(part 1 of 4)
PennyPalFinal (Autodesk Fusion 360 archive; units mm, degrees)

design "PennyPalFinal" references "switch", "boost", "PCB&CoinChute1", "battery snap fit", "annular-snap-speaker1", "solenoid", "mainPCB"
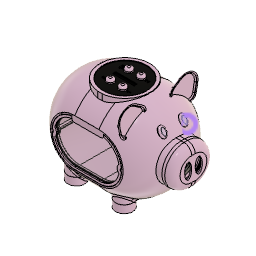
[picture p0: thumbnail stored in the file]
part number: 2026-05-30-10-11-40-978
part number: 2026-05-16-19-25-30-712
description: KiCad electronic assembly
part number: 2026-05-24-18-37-49-600
description: Part Number
part number: 2026-05-24-11-27-49-518
part number: 2026-05-24-18-37-49-601
sketch "piggysketch" plane through (0, 0, 0) normal (0, 0, 1) x axis (1, 0, 0)
  line L1 (-82.5, -65) -> (82.5, -65)
  line L2 (-82.5, 65) -> (-82.5, -65)
  line L3 (82.5, 65) -> (-82.5, 65)
  line L4 (82.5, -65) -> (82.5, 65)
  line L5 (-82.5, 65) -> (82.5, -65)
  line L6 (82.5, 65) -> (-82.5, -65)
  line L7 (82.5, 0) -> (-82.5, 0)
  circle C1 centre (-17.5, 0) radius 65
  circle C2 centre (17.5, 0) radius 65
  point P6 (0, 0)
  point P1 (0, 0)
  point P9 (-82.5, 0)
  point P10 (82.5, 0)
  point P4 (-82.5, 65)
  point P5 (82.5, 65)
  point P3 (-82.5, -65)
  horizontal L1
  perpendicular L1 L2
  parallel L1 L3
  parallel L2 L4
  coincident L5 P6
  coincident L6 P6
  coincident P1 P6
  midpoint L2 P9
  midpoint L4 P10
  dimension "d1" distance P4 P5 = 165
  dimension "d2" distance P3 P4 = 130
  dimension "d3" diameter C1 = 130
  dimension "d4" diameter C2 = 130
revolve "Revolve1" sketch "piggysketch" AlongAngle 360
shell "Shell1" innerThickness 2
work_plane "WorkPlane1" AlongDistance 83
sketch "facesketch" plane through (83, 0, 0) normal (1, 0, 0) x axis (0, 1, 0)
  line L1 (-30, -22.5) -> (30, -22.5)
  line L2 (-30, 22.5) -> (-30, -22.5)
  line L3 (30, 22.5) -> (-30, 22.5)
  line L4 (30, -22.5) -> (30, 22.5)
  line L5 (30, 22.5) -> (-30, -22.5)
  line L6 (30, 0) -> (-30, 0)
  line L7 (-30, 0) -> (0, 0)
  line L8 (-29.1264, 64.0008) -> (-30, 0)
  line L9 (0, 65.16) -> (-29.1264, 64.0008)
  line L10 (0, 0) -> (0, 65.16)
  line L11 (0, 32.58) -> (-30, 32.58)
  line L12 (-15, 22.5) -> (-15, 65.16)
  line L13 (-15, 0) -> (-15, 21.2132)
  line L14 (-29.4017, 43.83) -> (-15, 43.83)
  curve K1 (-15, 42.5) -> (-15, 27.5)
  curve K2 (-20.3395, 35) -> (-9.6605, 35)
  line L15 (-44.7548, 40.1162) -> (-26.9747, 52.3166)
  line L16 (-62.3715, 58.4644) -> (-60.0051, 46.3533)
  line L17 (-27.0389, 69.0425) -> (-36.629, 75.5154)
  line L18 (-49.3045, 79.4031) -> (-31.4219, 51.5006)
  line L19 (-60.4086, 58.848) -> (-58.0422, 46.7368)
  line L20 (-28.1577, 67.3848) -> (-37.748, 73.8577)
  line L21 (-45.8864, 41.7654) -> (-28.1062, 53.9657)
  line L22 (27.3032, -17.9046) -> (27.9578, -18.4233)
  line L23 (31.5266, -21.1565) -> (30.8609, -20.6522)
  line L24 (28.7497, -21.5623) -> (30, -22.5)
  line L25 (-30, 22.5) -> (26.794, -20.0955)
  line L26 (-27.3032, -17.9046) -> (-27.9578, -18.4233)
  line L27 (-31.5266, -21.1565) -> (-30.8609, -20.6522)
  circle C1 centre (-7.5, 0) radius 22.5
  circle C2 centre (7.5, 0) radius 22.5
  closed curve K3 centre (-15, 35)
  closed curve K4 centre (15, 35)
  arc A1 centre (-50.3315, 48.2434) radius 9.8565 clockwise from (-44.7548, 40.1162) to (-60.0051, 46.3533)
  arc A2 centre (-32.6982, 60.6577) radius 10.116 clockwise from (-27.0389, 69.0425) to (-26.9747, 52.3166)
  arc A3 centre (-45.9752, 61.6681) radius 16.7063 clockwise from (-62.3715, 58.4644) to (-36.629, 75.5154)
  arc A4 centre (-45.9752, 61.6681) radius 14.7063 clockwise from (-60.4086, 58.848) to (-37.748, 73.8577)
  arc A5 centre (-32.6982, 60.6577) radius 8.116 clockwise from (-28.1577, 67.3848) to (-28.1062, 53.9657)
  arc A6 centre (-50.3315, 48.2434) radius 7.8565 clockwise from (-45.8864, 41.7654) to (-58.0422, 46.7368)
  arc A7 centre (29.4022, -19.5471) radius 1.8301 clockwise from (30.8609, -20.6522) to (27.9578, -18.4233)
  arc A8 centre (29.4022, -19.5471) radius 2.6652 clockwise from (27.206, -21.0572) to (27.3032, -17.9046)
  arc A9 centre (29.4022, -19.5471) radius 2.6652 clockwise from (31.5266, -21.1565) to (28.3703, -22.0045)
  arc A10 centre (-29.4022, -19.5471) radius 1.8301 clockwise from (-27.9578, -18.4233) to (-30.8609, -20.6522)
  arc A11 centre (-29.4022, -19.5471) radius 2.6652 clockwise from (-27.3032, -17.9046) to (-27.206, -21.0572)
  arc A12 centre (-29.4022, -19.5471) radius 2.6652 clockwise from (-28.3703, -22.0045) to (-31.5266, -21.1565)
  arc A13 centre (0, 2.7271) radius 37.6367 clockwise from (28.3703, -22.0045) to (-28.3703, -22.0045)
  arc A14 centre (0, 2.7271) radius 36.1367 clockwise from (27.206, -21.0572) to (-27.206, -21.0572)
  point P6 (0, 0)
  point P1 (0, 0)
  point P7 (-30, 0)
  point P8 (30, 0)
  point P11 (0, 0)
  point P16 (0, 32.58)
  point P18 (-15, 0)
  point P19 (-15, 22.5)
  point P20 (-15, 21.2132)
  point P21 (-15, 43.83)
  point P22 (-29.4017, 43.83)
  point P24 (-15, 27.5)
  point P25 (-15, 42.5)
  point P26 (-9.6605, 35)
  point P27 (-20.3395, 35)
  point P23 (-15, 35)
  point P57 (26.794, -20.0955)
  point P51 (27.3032, -17.9046)
  point P64 (-27.3032, -17.9046)
  point P52 (31.5266, -21.1565)
  point P66 (-31.5266, -21.1565)
  point P53 (27.9578, -18.4233)
  point P61 (-27.9578, -18.4233)
  point P54 (30.8609, -20.6522)
  point P62 (-30.8609, -20.6522)
  point P55 (27.206, -21.0572)
  point P65 (-27.206, -21.0572)
  point P58 (28.3703, -22.0045)
  point P68 (-28.3703, -22.0045)
  point P4 (-30, 22.5)
  point P5 (30, 22.5)
  point P3 (-30, -22.5)
  horizontal L1
  perpendicular L1 L2
  parallel L1 L3
  parallel L2 L4
  coincident P6 L25
  coincident L5 P6
  coincident P1 P6
  midpoint L2 P7
  midpoint L4 P8
  coincident P7 C1
  coincident P8 C2
  horizontal L7
  vertical L10
  coincident P6 P11
  midpoint L10 P16
  midpoint L7 P18
  tangent C2 L13
  coincident L3 P19
  coincident C1 P20
  collinear L12 L13
  midpoint L12 P21
  coincident L8 P22
  coincident K3 P24
  coincident K3 P25
  coincident K3 P26
  coincident K3 P27
  coincident L12 P23
  perpendicular L14 K1
  symmetric L10 K3 K4
  tangent L15 A1
  tangent L16 A1
  tangent L15 A2
  tangent L17 A2
  tangent L16 A3
  tangent L17 A3
  concentric A7 A8
  collinear L24 L25
  coincident P57 A8
  concentric A8 A9
  symmetric L10 P51 P64
  symmetric L10 P52 P66
  symmetric L10 P53 P61
  symmetric L10 A7 A10
  symmetric L10 P54 P62
  symmetric L10 P55 P65
  symmetric L10 P58 P68
  symmetric L10 A8 A11
  symmetric L10 A9 A12
  dimension "d8" distance P4 P5 = 60
  dimension "d9" distance P3 P4 = 45
  dimension "d13" diameter C1 = 45
  dimension "d14" diameter C2 = 45
  dimension "d17" distance K3 = 15
  dimension "d24" = -2
revolve "Revolve3" sketch "facesketch" AlongAngle 360
move "Move1"
shell "Shell2" innerThickness 2
combine "Combine1"
extrude "Extrude1" new body sketch "facesketch" profile of K3 K4 against normal blind 5 bodies "eyer", "eyel"
fillet "Fillet1" radius 2.5
move "Move2"
extrude "Extrude2" new body sketch "facesketch" profile of L15 L16 L17 A1 A2 A3 A6 L21 A5 A4 L20 L19 against normal blind 4
extrude "Extrude3" cut sketch "facesketch" profile of A6 L21 A5 A4 L20 L19 against normal blind 2
move "Move3"
fillet "Fillet4" radius 5
fillet "Fillet5" radius 1.5
mirror "Mirror1" mirrorStitchTolerance 0.1
split "Split2" bodies "leftear", "rightear"
work_plane "WorkPlane2" AlongDistance -64
sketch "bottomsketch" plane through (0, 0, -64) normal (0, 0, 1) x axis (1, 0, 0)
  line L1 (-66.7381, 65.3483) -> (66.7381, 65.3483)
  line L2 (-66.7381, -65.3483) -> (-66.7381, 65.3483)
  line L3 (66.7381, -65.3483) -> (-66.7381, -65.3483)
  line L4 (66.7381, 65.3483) -> (66.7381, -65.3483)
  line L5 (-66.7381, -65.3483) -> (66.7381, 65.3483)
  line L6 (66.7381, -65.3483) -> (-66.7381, 65.3483)
  line L7 (66.7381, 0) -> (-66.7381, 0)
  line L8 (66.7381, 32.2443) -> (-66.7381, 32.2443)
  circle C1 centre (31.2041, 32.2443) radius 12.5
  circle C2 centre (-37.8687, 32.2443) radius 12.5
  circle C3 centre (-37.8687, -32.2443) radius 12.5
  circle C4 centre (31.2041, -32.2443) radius 12.5
  circle C5 centre (31.2041, 32.2443) radius 10.5
  circle C6 centre (-37.8687, 32.2443) radius 10.5
  circle C7 centre (31.2041, -32.2443) radius 10.5
  circle C8 centre (-37.8687, -32.2443) radius 10.5
  point P6 (0, 0)
  point P1 (0, 0)
  point P7 (-66.7381, 0)
  point P8 (66.7381, 0)
  point P9 (-66.7381, 32.2443)
  point P10 (66.7381, 32.2443)
  point P11 (31.2041, 32.2443)
  point P12 (-37.8687, 32.2443)
  horizontal L1
  perpendicular L1 L2
  parallel L1 L3
  parallel L2 L4
  coincident L5 P6
  coincident L6 P6
  coincident P1 P6
  midpoint L2 P7
  midpoint L4 P8
  coincident L2 P9
  coincident L4 P10
  perpendicular L4 L8
  coincident L8 P11
  coincident L8 P12
  symmetric L7 C1 C4
  symmetric L7 C2 C3
  dimension "d42" diameter C1 = 25
  dimension "d43" diameter C2 = 25
  dimension "d48" = -2
  dimension "d49" = -2
  dimension "d50" = -2
  dimension "d51" = -2
extrude "Extrude7" new body sketch "bottomsketch" profile of C1 C2 C3 C4 C5 C6 C7 C8 along normal blind 30
extrude "Extrude8" add sketch "bottomsketch" profile of C1 C2 C3 C4 C5 C6 C7 C8 against normal blind 2
split "Split3" bodies "frontleftleg", "frontrightleg"
split "Split4" bodies "leftleg", "rightleg"
combine "Combine3"
fillet "Fillet6" radius 5
combine "Combine5"
split "Split5" bodies "righteye (1)", "left eye (1)"
combine "Combine6"
work_plane "WorkPlane3" AlongDistance -83
coil_primitive "CoilPrimitive1" Diameter 8 SectionSize 4 TaperAngle 20 Pitch -4 bodies "tl"
move_face "MoveFace1"
fillet "Fillet7" radius 1.5
sketch "chambersketch" plane through (0, 0, 0) normal (0, 1, 0) x axis (1, 0, 0)
  curve K1 (-20.7097, 55.2331) -> (-20.7097, 55.2331)
  line L1 (-17.5, 65) -> (-17.5, -65)
  curve K2 (-20.7097, 55.2331) -> (-20.7097, 55.2331)
  curve K3 (72.477, -32.5988) -> (66.08, -41.7346)
  curve K4 (72.6004, -31.0474) -> (72.477, -32.5988)
  curve K5 (66.08, -41.7346) -> (72.6004, -31.0474)
  curve K6 (66.08, -41.7346) -> (72.477, -32.5988)
  curve K7 (72.6004, -31.0474) -> (66.08, -41.7346)
  curve K8 (72.477, -32.5988) -> (72.6004, -31.0474)
  curve K9 (47.5, -35.3893) -> (46, -36.887)
  curve K10 (47.5, -35.3893) -> (48, -35.3882)
  line L2 (48, -33.4728) -> (48, -35.3882)
  curve K11 (44, -38.286) -> (48, -33.4728)
  line L3 (44, -54.9082) -> (44, -38.286)
  curve K12 (48, -54.6237) -> (44, -54.9082)
  line L4 (48, -53.8848) -> (48, -54.6237)
  curve K13 (47.5, -54.1873) -> (48, -53.8848)
  curve K14 (46, -54.438) -> (47.5, -54.1873)
  line L5 (46, -36.887) -> (46, -54.438)
  curve K15 (48, -33.4728) -> (44, -38.286)
  line L6 (48, -33.4728) -> (48, -35.3882)
  curve K16 (48, -35.3882) -> (47.5, -35.3893)
  curve K17 (46, -36.887) -> (47.5, -35.3893)
  line L7 (46, -36.887) -> (46, -54.438)
  curve K18 (47.5, -54.1873) -> (46, -54.438)
  curve K19 (48, -53.8848) -> (47.5, -54.1873)
  line L8 (48, -53.8848) -> (48, -54.6237)
  curve K20 (44, -54.9082) -> (48, -54.6237)
  line L9 (44, -54.9082) -> (44, -38.286)
  curve K21 (46.2286, 48.2323) -> (17.5, 61.8997)
  line L10 (17.5, 65) -> (17.5, 61.8997)
  curve K22 (17.5, 61.8997) -> (46.2286, 48.2323)
  curve K23 (46.2286, 48.2323) -> (17.5, 51.1979)
  line L11 (17.5, 51.1979) -> (17.5, -65)
  curve K24 (17.5, 51.1979) -> (46.2286, 48.2323)
  line L12 (-17.5, 65) -> (-17.5, -65)
  curve K25 (17.5, 51.1979) -> (17.5, 61.8997)
  line L13 (17.5, 51.1979) -> (17.5, -65)
  curve K26 (17.5, 61.8997) -> (17.5, 51.1979)
  line L14 (17.5, 65) -> (17.5, 61.8997)
  line L15 (27.5, -30) -> (-27.5, -30)
  line L16 (37.5, 20) -> (37.5, -20)
  line L17 (-27.5, 30) -> (27.5, 30)
  line L18 (-37.5, -20) -> (-37.5, 20)
  line L19 (37.5, 30) -> (-37.5, -30)
  line L20 (-37.5, 30) -> (37.5, -30)
  line L21 (39.5, 20) -> (39.5, -20)
  line L22 (-27.5, 32) -> (27.5, 32)
  line L23 (-39.5, -20) -> (-39.5, 20)
  line L24 (27.5, -32) -> (-27.5, -32)
  curve K27 (78.4835, -22.4948) -> (78.0186, -22.5)
  curve K28 (78.4835, 22.4948) -> (78.0186, 22.5)
  line L25 (0, -32) -> (0, -30)
  line L26 (36, -28.4705) -> (36, -25.2678)
  line L27 (-36, -28.4705) -> (-36, -25.2678)
  arc A1 centre (-27.5, -20) radius 10 clockwise from (-27.5, -30) to (-37.5, -20)
  arc A2 centre (27.5, -20) radius 10 clockwise from (37.5, -20) to (27.5, -30)
  arc A3 centre (27.5, 20) radius 10 clockwise from (27.5, 30) to (37.5, 20)
  arc A4 centre (-27.5, 20) radius 10 clockwise from (-37.5, 20) to (-27.5, 30)
  arc A5 centre (27.5, 20) radius 12 clockwise from (27.5, 32) to (39.5, 20)
  arc A6 centre (-27.5, 20) radius 12 clockwise from (-39.5, 20) to (-27.5, 32)
  arc A7 centre (-27.5, -20) radius 12 clockwise from (-27.5, -32) to (-39.5, -20)
  arc A8 centre (27.5, -20) radius 12 clockwise from (39.5, -20) to (27.5, -32)
  closed curve K29 centre (78.0183, 0)
  closed curve K30 centre (78.0183, 0)
  point P35 (0, 0)
  point P1 (0, 0)
  point P31 (-37.5, -30)
  point P32 (37.5, -30)
  point P33 (37.5, 30)
  point P34 (-37.5, 30)
  point P65 (0, -30)
  point P66 (0, -32)
  point P67 (36, -25.2678)
  point P68 (-36, -25.2678)
  point P69 (-36, -28.4705)
  point P70 (36, -28.4705)
  horizontal L15
  perpendicular L15 L16
  parallel L15 L17
  parallel L16 L18
  coincident L19 P35
  coincident L20 P35
  coincident P1 P35
  coincident P31 L18
  coincident P31 L15
  tangent L18 A1
  tangent L15 A1
  coincident P32 L15
  coincident P32 L16
  tangent L15 A2
  tangent L16 A2
  equal A1 A2
  coincident P33 L16
  coincident P33 L17
  tangent L16 A3
  tangent L17 A3
  equal A1 A3
  coincident P34 L17
  coincident P34 L18
  tangent L17 A4
  tangent L18 A4
  equal A1 A4
  midpoint L15 P65
  midpoint L24 P66
  coincident A2 P67
  coincident A1 P68
  vertical L27
  coincident A7 P69
  coincident A8 P70
  dimension "d74" distance P33 P34 = 75
  dimension "d75" distance P32 P33 = 60
  dimension "d76" radius A1 = 10
  dimension "d81" = 2
extrude "Extrude11" new body sketch "chambersketch" profile of L1 L11 L12 L13 L15 L16 L17 L18 A1 A2 A3 A4 L22 L23 A7 A6 L24 A5 A8 L21 against normal blind 140
extrude "Extrude12" add sketch "chambersketch" profile of L1 L11 L12 L13 L15 L16 L17 L18 A1 A2 A3 A4 L22 L23 A7 A6 L24 A5 A8 L21 along normal blind 140
split "Split6"
split "Split7" bodies "chamber"
extrude "Extrude13" cut sketch "chambersketch" profile of L1 L11 L12 L13 L15 L16 L17 L18 A1 A2 A3 A4 against normal blind 230
extrude "Extrude14" cut sketch "chambersketch" profile of L1 L11 L12 L13 L15 L16 L17 L18 A1 A2 A3 A4 along normal blind 250
combine "Combine7"
extrude "Extrude15" cut sketch "chambersketch" profile of L1 L11 L12 L13 L15 L16 L17 L18 A1 A2 A3 A4 against normal blind 160
extrude "Extrude16" cut sketch "chambersketch" profile of L1 L11 L12 L13 L15 L16 L17 L18 A1 A2 A3 A4 along normal blind 140
external_derived "Sketch1"
derived_instance "DerivedInstance1"
derived_instance "DerivedInstance1"
derived_instance "DerivedInstance2"
derived_instance "DerivedInstance3"
derived_instance "DerivedInstance1"
derived_instance "DerivedInstance1"
derived_instance "DerivedInstance2"
derived_instance "DerivedInstance3"
derived_instance "DerivedInstance4"
derived_instance "DerivedInstance5"
derived_instance "DerivedInstance6"
derived_instance "DerivedInstance7"
derived_instance "DerivedInstance1"
derived_instance "DerivedInstance2"
derived_instance "DerivedInstance3"
derived_instance "DerivedInstance4"
derived_instance "DerivedInstance1"
derived_instance "DerivedInstance2"
derived_instance "DerivedInstance3"
derived_instance "DerivedInstance4"
derived_instance "DerivedInstance1"
derived_instance "DerivedInstance2"
derived_instance "DerivedInstance3"
derived_instance "DerivedInstance4"
joint "Assemble1"
joint "Assemble5"
as_built_joint "As-built1"
as_built_joint "As-built1"
position "Position1"
sketch "chuteoutline" plane through (0, 0, 62) normal (0, 0, 1) x axis (-1, 0, 0)
  line L1 (32.744, -24.885) -> (32.744, 24.885)
  line L2 (-23.168, -26.885) -> (30.744, -26.885)
  line L3 (-25.168, -9.5) -> (-25.168, -24.885)
  line L4 (-25.168, 24.885) -> (-25.168, 9.5)
  line L5 (30.744, 26.885) -> (-23.168, 26.885)
  line L6 (17.5, 5.5) -> (17.5, -5.5)
  line L7 (-14.9, 7.5) -> (15.5, 7.5)
  line L8 (15.6, -2.35) -> (-14.6, -2.35)
  line L9 (15.6, 2.35) -> (15.6, -2.35)
  line L10 (-14.6, 2.35) -> (15.6, 2.35)
  line L11 (15.5, -7.5) -> (-14.9, -7.5)
  line L12 (-11, 7.5) -> (-14.9, 7.5)
  line L13 (-14.9, -7.5) -> (-11, -7.5)
  line L14 (-16.9, -5.5) -> (-16.9, 5.5)
  line L15 (-36, 36) -> (36, 36)
  line L16 (-36, -36) -> (-36, 36)
  line L17 (36, -36) -> (-36, -36)
  line L18 (36, 36) -> (36, -36)
  line L19 (-36, -36) -> (36, 36)
  line L20 (36, -36) -> (-36, 36)
  circle C1 centre (0, 0) radius 34.1551
  circle C2 centre (0, 0) radius 31.5287
  circle C3 centre (0, 0) radius 34.1551
  arc A1 centre (30.744, -24.885) radius 2 clockwise from (32.744, -24.885) to (30.744, -26.885)
  arc A2 centre (-23.168, -24.885) radius 2 clockwise from (-23.168, -26.885) to (-25.168, -24.885)
  arc A3 centre (-23.168, 24.885) radius 2 clockwise from (-25.168, 24.885) to (-23.168, 26.885)
  arc A4 centre (30.744, 24.885) radius 2 clockwise from (30.744, 26.885) to (32.744, 24.885)
  arc A5 centre (15.5, 5.5) radius 2 clockwise from (15.5, 7.5) to (17.5, 5.5)
  arc A6 centre (15.5, -5.5) radius 2 clockwise from (17.5, -5.5) to (15.5, -7.5)
  arc A7 centre (-14.9, -5.5) radius 2 clockwise from (-14.9, -7.5) to (-16.9, -5.5)
  arc A8 centre (-14.9, 5.5) radius 2 clockwise from (-16.9, 5.5) to (-14.9, 7.5)
  circle C4 centre (0, 0) radius 36.1551
  circle C5 centre (0, 0) radius 31.5287
  point P43 (0, 0)
  point P4 (0, 0)
  point P41 (-36, -36)
  point P42 (36, -36)
  point P40 (-36, 36)
  horizontal L15
  perpendicular L15 L16
  parallel L15 L17
  parallel L16 L18
  coincident L19 P43
  coincident L20 P43
  coincident P4 P43
  dimension "d94" distance P41 P42 = 72
  dimension "d95" distance P40 P41 = 72
  dimension "d98" = 2
position "Position2"
extrude "Extrude27" new body sketch "chuteoutline" profile of C1 C3 L1 L2 A2 L3 L4 A3 L5 L15 L16 L17 L18 C4 against normal blind 8
extrude "Extrude28" cut sketch "chuteoutline" profile of C1 C2 C3 L1 L2 L3 L4 L5 against normal blind 20
extrude "Extrude29" cut sketch "chuteoutline" profile of C1 C2 C3 L1 L2 L3 L4 L5 along normal blind 17
extrude "Extrude30" add of existing geometry blind 1
extrude "Extrude31" add sketch "chuteoutline" profile of C1 C2 C3 L1 L2 L3 L4 L5 to an object
extrude "Extrude32" add of existing geometry to an object
base_feature "Base Feature1"
base_feature "Base Feature1"
base_feature "Base Feature1"
base_feature "Base Feature1"
base_feature "Base Feature1"
base_feature "Base Feature1"
base_feature "Base Feature1"
base_feature "Base Feature1"
base_feature "Base Feature1"
base_feature "Base Feature1"
base_feature "Base Feature1"
base_feature "Base Feature1"
base_feature "Base Feature1"
base_feature "Base Feature1"
base_feature "Base Feature1"
base_feature "Base Feature1"
base_feature "Base Feature1"
base_feature "Base Feature1"
base_feature "Base Feature1"
base_feature "Base Feature1"
base_feature "Base Feature1"
base_feature "Base Feature1"
base_feature "Base Feature1"
base_feature "Base Feature1"
base_feature "Base Feature1"
base_feature "Base Feature1"
base_feature "Base Feature1"
base_feature "Base Feature1"
base_feature "Base Feature1"
base_feature "Base Feature1"
base_feature "Base Feature1"
base_feature "Base Feature1"
base_feature "Base Feature1"
base_feature "Base Feature1"
base_feature "Base Feature1"
as_built_joint "As-built1"
joint "Assemble" alignAngle 0 alignOffsetX 0 alignOffsetY -16 alignOffsetZ 8
sketch "Sketch9" plane through (0, 0, 0) normal (1, 0, 0) x axis (0, 1, 0)
  circle C1 centre (0, 0) radius 9.15
  point P1 (0, 0)
  point P2 (0, 0)
  coincident P1 P2
  dimension "d133" diameter C1 = 18.3
extrude "Extrude33" new body sketch "Sketch9" along normal blind 32.77 bodies "battery"
extrude "Extrude34" add of existing geometry blind 32.77
move "Move4"
external_derived "Sketch1"
derived_instance "DerivedInstance3"
move "Move1"
position "Position4"
work_plane "WorkPlane4" AlongDistance -55
split "Split8" bodies "piggy (1)"
remove_body "RemoveBody1"
remove_body "RemoveBody2"
remove_body "RemoveBody3"
remove_body "RemoveBody4"
remove_body "RemoveBody5"
remove_body "RemoveBody6"
remove_body "RemoveBody7"
remove_body "RemoveBody8"
remove_body "RemoveBody9"
remove_body "RemoveBody10"
remove_body "RemoveBody11"
remove_body "RemoveBody12"
remove_body "RemoveBody13"
remove_body "RemoveBody14"
remove_body "RemoveBody15"
remove_body "RemoveBody16"
remove_body "RemoveBody17"
remove_body "RemoveBody18"
remove_body "RemoveBody19"
remove_body "RemoveBody20"
scale "Scale2" ScaleZ 1.1743
move "Move6"
split "Split9" bodies "piggy (1) (2)", "piggy (1) (3)"
remove_body "RemoveBody21"
remove_body "RemoveBody22"
remove_body "RemoveBody23"
sketch "Sketch11" plane through (83, 0, 0) normal (1, 0, 0) x axis (0, 1, 0)
  curve K1 (7.5, -26.0896) -> (7.5, 26.0896)
  curve K2 (7.5, 26.0896) -> (-7.5, 26.0896)
  curve K3 (-7.5, 26.0896) -> (-7.5, -26.0896)
  curve K4 (-7.5, -26.0896) -> (7.5, -26.0896)
  curve K5 (-7.5521, -24.0903) -> (7.5521, -24.0903)
  curve K6 (-7.5521, 24.0903) -> (-7.5521, -24.0903)
  curve K7 (7.5521, 24.0903) -> (-7.5521, 24.0903)
  curve K8 (7.5521, -24.0903) -> (7.5521, 24.0903)
  curve K9 (-7.6042, -22.091) -> (7.6042, -22.091)
  curve K10 (-7.6042, 22.091) -> (-7.6042, -22.091)
  curve K11 (7.6042, 22.091) -> (-7.6042, 22.091)
  curve K12 (7.6042, -22.091) -> (7.6042, 22.091)
  dimension "d147" = 2
  dimension "d148" = 2
external_derived "Sketch1"
derived_instance "DerivedInstance4"
derived_instance "DerivedInstance1"
derived_instance "DerivedInstance2"
derived_instance "DerivedInstance3"
derived_instance "DerivedInstance4"
remove_body "RemoveBody24"
position "Position7"
sketch "Sketch16" plane through (0, 0, 32) normal (0, 0, 1) x axis (-1, 0, 0)
  line L1 (27.5, 55.6866) -> (27.5, -55.6866)
  line L2 (-17.5, 56.5774) -> (17.5, 56.5774)
  line L3 (-27.5, -55.6866) -> (-27.5, 55.6866)
  line L4 (17.5, -56.5774) -> (-17.5, -56.5774)
  line L5 (-36, -36) -> (36, 36)
  line L6 (36, -36) -> (-36, 36)
  line L7 (-48, -36) -> (48, 36)
  line L8 (48, -36) -> (-48, 36)
  line L9 (-27.5, 55.6866) -> (-27.5, -55.6866)
  curve K1 (-39.5, 57.8014) -> (-27.5, 55.6866)
  line L10 (-39.5, -57.8014) -> (-39.5, 57.8014)
  curve K2 (-39.5, -57.8014) -> (-27.5, -55.6866)
  line L11 (39.5, 57.8014) -> (39.5, -57.8014)
  curve K3 (27.5, 55.6866) -> (39.5, 57.8014)
  line L12 (27.5, -55.6866) -> (27.5, 55.6866)
  curve K4 (27.5, -55.6866) -> (39.5, -57.8014)
  line L13 (-39.5, -36) -> (-36, -36)
  line L14 (-37.5, -36) -> (-37.5, -34)
  line L15 (36, -46) -> (-36, -46)
  line L16 (-36, 46) -> (36, 46)
  line L17 (-36, -46) -> (-36, 46)
  line L18 (36, 46) -> (36, -46)
  line L19 (-36, -46) -> (36, 46)
  line L20 (36, -46) -> (-36, 46)
  line L21 (18.5, -8.5) -> (-18.5, 8.5)
  line L22 (-18.5, -8.5) -> (18.5, 8.5)
  line L23 (-36, 36) -> (36, 36)
  line L24 (-36, -36) -> (-36, 36)
  line L25 (36, -36) -> (-36, -36)
  line L26 (36, 36) -> (36, -36)
  line L27 (-36, -36) -> (36, 36)
  line L28 (36, -36) -> (-36, 36)
  line L29 (17.5, 7.5) -> (-19.9, 7.5)
  line L30 (17.5, -7.5) -> (17.5, 7.5)
  line L31 (-19.9, -7.5) -> (17.5, -7.5)
  line L32 (-19.9, 7.5) -> (-19.9, -7.5)
  line L33 (17.5, 46) -> (27.5, 46)
  line L34 (17.5, 36) -> (17.5, 46)
  line L35 (27.5, 36) -> (17.5, 36)
  line L36 (27.5, 46) -> (27.5, 36)
  line L37 (27.5, 46) -> (17.5, 36)
  line L38 (0, 36) -> (0, 46)
  line L39 (17.5, 0) -> (0, 0)
  line L40 (15.6, -2.35) -> (-14.6, -2.35)
  line L41 (15.6, 2.35) -> (15.6, -2.35)
  line L42 (-14.6, 2.35) -> (15.6, 2.35)
  line L43 (15.5, 7.5) -> (-14.9, 7.5)
  line L44 (17.5, -5.5) -> (17.5, 5.5)
  line L45 (-14.9, -7.5) -> (15.5, -7.5)
  line L46 (-16.9, 1.15) -> (-16.9, -1.15)
  line L47 (-16.9, 5.5) -> (-16.9, -5.5)
  line L48 (15.5, -7.5) -> (-14.9, -7.5)
  line L49 (-21.9, -9.5) -> (19.5, -9.5)
  line L50 (-21.9, 9.5) -> (-21.9, -9.5)
  line L51 (19.5, 9.5) -> (-21.9, 9.5)
  line L52 (19.5, -9.5) -> (19.5, 9.5)
  line L53 (-14.6, -2.35) -> (-14.6, 2.35)
  line L54 (-16.9, 5.5) -> (-16.9, -5.5)
  line L55 (-16.9, -5.5) -> (-16.9, 5.5)
  arc A1 centre (17.5, 0) radius 56.5774 clockwise from (17.5, 56.5774) to (27.5, 55.6866)
  arc A2 centre (-17.5, 0) radius 56.5774 clockwise from (-27.5, 55.6866) to (-17.5, 56.5774)
  arc A3 centre (-17.5, 0) radius 56.5774 clockwise from (-17.5, -56.5774) to (-27.5, -55.6866)
  arc A4 centre (17.5, 0) radius 56.5774 clockwise from (27.5, -55.6866) to (17.5, -56.5774)
  circle C1 centre (22.5, 41) radius 0.9
  circle C2 centre (22.5, 41) radius 2
  arc A5 centre (15.5, 5.5) radius 2 clockwise from (15.5, 7.5) to (17.5, 5.5)
  arc A6 centre (15.5, -5.5) radius 2 clockwise from (17.5, -5.5) to (15.5, -7.5)
  arc A7 centre (-14.9, 5.5) radius 2 clockwise from (-16.9, 5.5) to (-14.9, 7.5)
  arc A8 centre (-14.9, 5.5) radius 2 clockwise from (-16.9, 5.5) to (-16.5703, 6.6)
  arc A9 centre (-14.9, 5.5) radius 2 clockwise from (-16.9, 5.5) to (-16.5703, 6.6)
  arc A10 centre (-14.9, -5.5) radius 2 clockwise from (-14.9, -7.5) to (-16.9, -5.5)
  arc A11 centre (-14.9, -5.5) radius 2 clockwise from (-16.5703, -6.6) to (-16.9, -5.5)
  arc A12 centre (-14.9, -5.5) radius 2 clockwise from (-16.5703, -6.6) to (-16.9, -5.5)
  arc A13 centre (-14.9, -5.5) radius 2 clockwise from (-14.9, -7.5) to (-16.9, -5.5)
  arc A14 centre (-14.9, 5.5) radius 2 clockwise from (-16.9, 5.5) to (-14.9, 7.5)
  arc A15 centre (-14.9, 5.5) radius 2 clockwise from (-16.9, 5.5) to (-14.9, 7.5)
  arc A16 centre (-14.9, -5.5) radius 2 clockwise from (-14.9, -7.5) to (-16.9, -5.5)
  point P16 (0, 0)
  point P1 (0, 0)
  point P21 (0, 0)
  point P30 (-39.5, -36)
  point P32 (-37.5, -36)
  point P39 (0, 0)
  point P44 (0, 0)
  point P49 (0, 0)
  point P54 (27.5, 46)
  point P58 (0, 46)
  point P59 (0, 36)
  point P60 (0, 0)
  point P61 (17.5, 0)
  point P63 (22.5, 41)
  point P14 (-36, -36)
  point P15 (36, -36)
  point P13 (-36, 36)
  point P19 (-48, -36)
  point P20 (48, -36)
  point P18 (-48, 36)
  point P37 (-36, -46)
  point P38 (36, -46)
  point P42 (18.5, -8.5)
  point P43 (-18.5, -8.5)
  point P41 (18.5, 8.5)
  point P47 (-36, -36)
  point P48 (36, -36)
  point P46 (-36, 36)
  point P55 (17.5, 46)
  point P57 (27.5, 36)
  coincident L5 P16
  coincident L6 P16
  coincident P1 P16
  coincident L7 P21
  coincident L8 P21
  coincident P16 P21
  coincident L10 P30
  perpendicular L10 L13
  coincident L13 P32
  perpendicular L13 L14
  horizontal L16
  perpendicular L16 L17
  parallel L17 L18
  coincident L19 P39
  coincident L20 P39
  coincident P1 P39
  coincident L21 P44
  coincident L22 P44
  coincident P21 P44
  horizontal L23
  perpendicular L23 L24
  parallel L23 L25
  parallel L24 L26
  coincident L27 P49
  coincident L28 P49
  coincident P21 P49
  horizontal L33
  vertical L34
  horizontal L35
  vertical L36
  coincident L16 P54
  coincident L12 P54
  midpoint L16 P58
  midpoint L23 P59
  coincident P44 P60
  midpoint L30 P61
  midpoint L37 P63
  concentric C1 C2
  perpendicular L29 L30
  perpendicular L29 L32
  perpendicular L31 L32
  collinear L31 L45
  collinear L30 L44
  collinear L29 L43
  dimension "d180" distance P14 P15 = 72
  dimension "d181" distance P13 P14 = 72
  dimension "d183" distance P19 P20 = 96
  dimension "d184" distance P18 P19 = 72
  dimension "d188" distance P37 P38 = 72
  dimension "d189" distance P42 P43 = 37
  dimension "d190" distance P41 P42 = 17
  dimension "d193" distance P47 P48 = 72
  dimension "d194" distance P46 P47 = 72
  dimension "d200" distance P54 P55 = 10
  dimension "d201" distance P54 P57 = 10
  dimension "d219" diameter C1 = 1.8
  dimension "d220" diameter C2 = 4
  dimension "d256" = -2
  dimension "d263" distance L32 L47 = 3
position "Position8"
as_built_joint "As-built1"
extrude "Extrude59" cut sketch "chambersketch" profile of L1 L11 L12 L13 L15 A1 A2 A7 L24 A8 L26 L27 against normal blind 50
extrude "Extrude60" cut sketch "chambersketch" profile of L1 L11 L12 L13 L15 A1 A2 A7 L24 A8 L26 L27 along normal blind 50
extrude "Extrude61" new body sketch "chambersketch" profile of L1 L11 L12 L13 L15 A1 A2 A7 L24 A8 L26 L27 against normal blind 50
extrude "Extrude62" add sketch "chambersketch" profile of L1 L11 L12 L13 L15 A1 A2 A7 L24 A8 L26 L27 along normal blind 50
extrude "Extrude63" cut sketch "Sketch16" profile of L32 L31 L30 L29 against normal blind 10
extrude "Extrude66" add sketch "Sketch16" profile of L32 L31 L30 L29 L43 L44 L45 L46 L47 L48 L52 L51 L50 L49 against normal blind 6
sketch "Sketch17" plane through (0, 0, 26) normal (0, 0, -1) x axis (1, 0, 0)
  line L1 (-17.5, -7.5) -> (19.9, -7.5)
  line L2 (-17.5, 7.5) -> (-17.5, -7.5)
  line L3 (19.9, 7.5) -> (-17.5, 7.5)
  line L4 (19.9, -7.5) -> (19.9, 7.5)
  line L5 (-19.5, 9.5) -> (21.9, 9.5)
  line L6 (-19.5, -9.5) -> (-19.5, 9.5)
  line L7 (21.9, -9.5) -> (-19.5, -9.5)
  line L8 (21.9, 9.5) -> (21.9, -9.5)
  line L9 (-15.6, -2.35) -> (14.6, -2.35)
  line L10 (-15.6, 2.35) -> (-15.6, -2.35)
  line L11 (14.6, 2.35) -> (-15.6, 2.35)
  line L12 (-15.5, 7.5) -> (14.9, 7.5)
  line L13 (-17.5, -5.5) -> (-17.5, 5.5)
  line L14 (14.9, -7.5) -> (-15.5, -7.5)
  line L15 (11, 1.35) -> (11, 7.5)
  line L16 (14.6, 1.35) -> (11, 1.35)
  line L17 (14.6, -1.35) -> (14.6, 1.35)
  line L18 (11, -1.35) -> (14.6, -1.35)
  line L19 (11, -7.5) -> (11, -1.35)
  line L20 (14.9, -7.5) -> (11, -7.5)
  line L21 (16.9, 5.5) -> (16.9, -5.5)
  line L22 (11, 7.5) -> (14.9, 7.5)
  line L23 (8.5, -7.5) -> (11, -7.5)
  line L24 (11, -1.35) -> (11, -7.5)
  line L25 (11, -1.35) -> (8.5, -1.35)
  line L26 (8.5, -7.5) -> (8.5, -1.35)
  line L27 (8.5, 1.35) -> (11, 1.35)
  line L28 (11, 7.5) -> (11, 1.35)
  line L29 (11, 7.5) -> (8.5, 7.5)
  line L30 (8.5, 1.35) -> (8.5, 7.5)
  line L31 (16.6, 4.35) -> (-16.6, 4.35)
  line L32 (16.6, -4.35) -> (16.6, 4.35)
  line L33 (-16.6, -4.35) -> (16.6, -4.35)
  line L34 (-16.6, 4.35) -> (-16.6, -4.35)
  line L35 (16.6, -4.35) -> (-16.6, 4.35)
  line L36 (-16.6, -4.35) -> (16.6, 4.35)
  line L37 (14.6, -2.35) -> (14.6, 2.35)
  line L38 (16.9, 5.5) -> (16.9, -5.5)
  arc A1 centre (-15.5, 5.5) radius 2 clockwise from (-17.5, 5.5) to (-15.5, 7.5)
  arc A2 centre (-15.5, -5.5) radius 2 clockwise from (-15.5, -7.5) to (-17.5, -5.5)
  arc A3 centre (14.9, -5.5) radius 2 clockwise from (16.9, -5.5) to (14.9, -7.5)
  arc A4 centre (14.9, 5.5) radius 2 clockwise from (14.9, 7.5) to (16.9, 5.5)
  arc A5 centre (14.9, -5.5) radius 2 clockwise from (16.9, -5.5) to (14.9, -7.5)
  arc A6 centre (14.9, 5.5) radius 2 clockwise from (14.9, 7.5) to (16.9, 5.5)
  point P46 (0, 0)
  point P1 (0, 0)
  horizontal L31
  perpendicular L31 L32
  parallel L31 L33
  parallel L32 L34
  coincident L35 P46
  coincident L36 P46
  coincident P1 P46
  dimension "d259" distance L9 L33 = 2
  dimension "d260" distance L10 L34 = 1
extrude "Extrude67" add sketch "Sketch17" profile of L1 L2 L3 L4 L12 L13 L14 L20 L21 L22 L23 L24 L28 L29 L30 L31 L32 L33 L34 against normal blind 2
component_from_bodies "Body->Comp"
sketch "chambercavity" plane through (0, 0, 0) normal (1, 0, 0) x axis (0, 1, 0)
  curve K1 (7.5, 26.0896) -> (-7.5, 26.0896)
  curve K2 (7.5, -26.0896) -> (7.5, 26.0896)
  curve K3 (-7.5, -26.0896) -> (7.5, -26.0896)
  curve K4 (-7.5, 26.0896) -> (-7.5, -26.0896)
  line L1 (-21.8956, -55) -> (21.8956, -55)
  curve K5 (21.8956, -55) -> (32.7614, -48.2323)
  curve K6 (32.7614, -48.2323) -> (40.0472, -51.1979)
  line L2 (56.5774, -32) -> (55.6866, -32)
  curve K7 (57.8014, -20) -> (55.6866, -32)
  curve K8 (55.6866, 32) -> (57.8014, 20)
  line L3 (55.6866, 32) -> (56.5774, 32)
  curve K9 (8.2014, 62) -> (31.6377, 56.7808)
  curve K10 (3.3454, 62.2218) -> (8.2014, 62)
  curve K11 (-8.2014, 62) -> (-3.3454, 62.2218)
  curve K12 (-31.6377, 56.7808) -> (-8.2014, 62)
  line L4 (-56.5774, 32) -> (-55.6866, 32)
  curve K13 (-57.8014, 20) -> (-55.6866, 32)
  curve K14 (-55.6866, -32) -> (-57.8014, -20)
  curve K15 (-40.0472, -51.1979) -> (-32.7614, -48.2323)
  curve K16 (-32.7614, -48.2323) -> (-21.8956, -55)
  curve K17 (-11.8257, 32.5988) -> (-11.0996, 41.7346)
  curve K18 (-15, 31.0474) -> (-11.8257, 32.5988)
  curve K19 (-11.0996, 41.7346) -> (-15, 31.0474)
  curve K20 (11.0996, 41.7346) -> (11.8257, 32.5988)
  curve K21 (15, 31.0474) -> (11.0996, 41.7346)
  curve K22 (11.8257, 32.5988) -> (15, 31.0474)
  curve K23 (-45.5258, 35.3893) -> (-45.3001, 36.887)
  curve K24 (-45.5258, 35.3893) -> (-45.1932, 35.3882)
  curve K25 (-45.3534, 38.286) -> (-46.6296, 33.4728)
  curve K26 (-17.6352, 54.6237) -> (-22.5353, 54.9082)
  curve K27 (-19.7165, 54.1873) -> (-19.7782, 53.8848)
  curve K28 (-21.1956, 54.438) -> (-19.7165, 54.1873)
  curve K29 (46.6296, 33.4728) -> (45.3534, 38.286)
  curve K30 (45.1932, 35.3882) -> (45.5258, 35.3893)
  curve K31 (45.3001, 36.887) -> (45.5258, 35.3893)
  curve K32 (19.7165, 54.1873) -> (21.1956, 54.438)
  curve K33 (19.7782, 53.8848) -> (19.7165, 54.1873)
  curve K34 (22.5353, 54.9082) -> (17.6352, 54.6237)
  line L5 (-54.9182, 35.1415) -> (-54.9182, -35.7012)
  line L6 (-66, -35.7012) -> (-54.9182, -35.7012)
  line L7 (-66, 35) -> (-66, -35.7012)
  line L8 (-54.9182, 35.1415) -> (-66, 35)
  line L9 (0, -74.9899) -> (0, 62.3117)
  line L10 (54.9182, 35.1415) -> (66, 35)
  line L11 (66, 35) -> (66, -35.7012)
  line L12 (54.9182, 35.1415) -> (54.9182, -35.7012)
  line L13 (66, -35.7012) -> (54.9182, -35.7012)
  arc A1 centre (0, 0) radius 65 clockwise from (56.5774, -32) to (40.0472, -51.1979)
  arc A2 centre (0, 0) radius 61.1637 clockwise from (57.8014, 20) to (57.8014, -20)
  arc A3 centre (0, 0) radius 65 clockwise from (31.6377, 56.7808) to (56.5774, 32)
  arc A4 centre (0, 0) radius 62.3117 clockwise from (-3.3454, 62.2218) to (3.3454, 62.2218)
  arc A5 centre (0, 0) radius 65 clockwise from (-56.5774, 32) to (-31.6377, 56.7808)
  arc A6 centre (0, 0) radius 61.1637 clockwise from (-57.8014, -20) to (-57.8014, 20)
  arc A7 centre (0, 0) radius 65 clockwise from (-40.0472, -51.1979) to (-56.5774, -32)
  arc A8 centre (0, 0) radius 57.3999 clockwise from (-46.6296, 33.4728) to (-45.1932, 35.3882)
  arc A9 centre (0, 0) radius 59.3528 clockwise from (-45.3534, 38.286) to (-22.5353, 54.9082)
  arc A10 centre (0, 0) radius 57.3999 clockwise from (-19.7782, 53.8848) to (-17.6352, 54.6237)
  arc A11 centre (0, 0) radius 58.4187 clockwise from (-45.3001, 36.887) to (-21.1956, 54.438)
  arc A12 centre (0, 0) radius 57.3999 clockwise from (45.1932, 35.3882) to (46.6296, 33.4728)
  arc A13 centre (0, 0) radius 58.4187 clockwise from (21.1956, 54.438) to (45.3001, 36.887)
  arc A14 centre (0, 0) radius 57.3999 clockwise from (17.6352, 54.6237) to (19.7782, 53.8848)
  arc A15 centre (0, 0) radius 59.3528 clockwise from (22.5353, 54.9082) to (45.3534, 38.286)
  point P61 (0, 62.3117)
  point P57 (-54.9182, -35.7012)
  point P66 (54.9182, -35.7012)
  point P58 (-54.9182, 35.1415)
  point P64 (54.9182, 35.1415)
  point P59 (-66, -35.7012)
  point P65 (66, -35.7012)
  point P60 (-66, 35)
  point P63 (66, 35)
  perpendicular L5 L6
  perpendicular L6 L7
  midpoint A4 P61
  vertical L9
  symmetric P57 L9 P66
  symmetric P58 L9 P64
  symmetric P59 L9 P65
  symmetric P60 L9 P63
extrude "Extrude68" cut sketch "chambercavity" profile of L5 L6 L7 L8 against normal blind 70 and along normal blind 80
extrude "Extrude69" cut sketch "chambercavity" profile of A1 L2 K7 A2 K8 L3 A3 L10 L11 L12 L13 against normal blind 100 and along normal blind 90
extrude "Extrude70" cut of existing geometry blind -420 second side blind -240
sketch "Sketch19" plane through (0, 0, 0) normal (0, 1, 0) x axis (1, 0, 0)
  line L1 (-17.5, -34.7705) -> (17.5, -34.7705)
  line L2 (17.5, 34.7705) -> (-17.5, 34.7705)
  line L3 (-17.5, -32.7705) -> (17.5, -32.7705)
  line L4 (17.5, 32.7705) -> (-17.5, 32.7705)
  line L5 (36, -28.4705) -> (36, -25.2678)
  line L6 (-36, -25.2678) -> (-36, -28.4705)
  line L7 (-36, -29.4404) -> (-36, -27.0491)
  line L8 (36, -29.4404) -> (36, -27.0491)
  arc A1 centre (-17.5, 0) radius 34.7705 clockwise from (-17.5, -34.7705) to (-17.5, 34.7705)
  arc A2 centre (17.5, 0) radius 34.7705 clockwise from (17.5, 34.7705) to (17.5, -34.7705)
  arc A3 centre (-17.5, 0) radius 32.7705 clockwise from (-17.5, -32.7705) to (-17.5, 32.7705)
  arc A4 centre (17.5, 0) radius 32.7705 clockwise from (17.5, 32.7705) to (17.5, -32.7705)
  point P18 (36, -29.4404)
  point P19 (36, -27.0491)
  point P20 (-36, -29.4404)
  point P21 (-36, -27.0491)
  parallel L6 L7
  parallel L5 L8
  coincident A2 P18
  coincident A4 P19
  coincident A1 P20
  coincident A3 P21
  dimension "d320" = 2
extrude "Extrude71" new body sketch "Sketch19" profile of A1 L1 A2 L2 L4 L3 A4 A3 against normal blind 55
extrude "Extrude72" add of existing geometry blind 55
sketch "Sketch20" plane through (0, 0, 34.7705) normal (0, 0, 1) x axis (-1, 0, 0)
  line L1 (17.5, 55) -> (17.5, -55)
  line L2 (-17.5, 55) -> (17.5, 55)
  line L3 (-17.5, -55) -> (-17.5, 55)
  line L4 (17.5, -55) -> (-17.5, -55)
  line L5 (-36, -50) -> (-36, 50)
  line L6 (17.5, 7.5) -> (-19.9, 7.5)
  line L7 (-19.9, 7.5) -> (-19.9, -7.5)
  line L8 (-16.6, 4.35) -> (-16.6, -4.35)
  line L9 (16.6, 4.35) -> (-16.6, 4.35)
  line L10 (-16.6, -4.35) -> (16.6, -4.35)
  line L11 (-19.9, -7.5) -> (17.5, -7.5)
  line L12 (17.5, -7.5) -> (17.5, 7.5)
  line L13 (16.6, -4.35) -> (16.6, 4.35)
  line L14 (36, -50) -> (36, 50)
  line L15 (-21.9, 9.5) -> (-21.9, -9.5)
  line L16 (-21.9, -9.5) -> (19.5, -9.5)
  line L17 (19.5, 9.5) -> (-21.9, 9.5)
  line L18 (19.5, -9.5) -> (19.5, 9.5)
  line L19 (36, 50) -> (-36, 50)
  line L20 (36, -50) -> (-36, -50)
  point P6 (-36, 50)
  point P22 (-36, 50)
  point P16 (36, 50)
  point P23 (36, 50)
  point P7 (-36, -50)
  point P24 (-36, -50)
  point P17 (36, -50)
  point P25 (36, -50)
  coincident P6 P22
  coincident P16 P23
  coincident P7 P24
  coincident P17 P25
sketch "Sketch21" plane through (0, 0, 0) normal (0, 1, 0) x axis (1, 0, 0)
  line L1 (-19.5, -26) -> (21.9, -26)
  line L2 (-19.5, -26) -> (-19.5, -30)
  line L3 (21.9, -26) -> (21.9, -30)
  line L4 (27.5, -30) -> (-27.5, -30)
  line L5 (-27.5, -32) -> (27.5, -32)
  line L6 (-36, -25.2678) -> (-36, -28.4705)
  line L7 (36, -28.4705) -> (36, -25.2678)
  line L8 (-36, -29.5) -> (-36, -28.4705)
  line L9 (36, -29.5) -> (36, -28.2236)
  line L10 (-19.5, -32) -> (-19.5, -30)
  line L11 (21.9, -32) -> (21.9, -30)
  line L12 (16.6, -28) -> (16.6, -26)
  line L13 (16.6, -26) -> (16.6, -28)
  line L14 (-16.6, -28) -> (-16.6, -26)
  line L15 (-16.6, -26) -> (-16.6, -28)
  line L16 (-19.5, -26) -> (-19.5, -30)
  line L17 (-19.5, -30) -> (-19.5, -26)
  line L18 (21.9, -26) -> (21.9, -30)
  line L19 (21.9, -30) -> (21.9, -26)
  line L20 (16.6, -28) -> (16.6, -26)
  line L21 (-16.6, -28) -> (-16.6, -26)
  line L22 (-17.5, -32) -> (-17.5, -28)
  line L23 (19.9, -32) -> (19.9, -28)
  line L24 (19.9, -28) -> (16.6, -28)
  line L25 (-17.5, -28) -> (-16.6, -28)
  line L26 (27.5, -30) -> (-27.5, -30)
  line L27 (36, -28.4705) -> (36, -25.2678)
  line L28 (-27.5, -32) -> (27.5, -32)
  line L29 (-36, -25.2678) -> (-36, -28.4705)
  arc A1 centre (-27.5, -20) radius 10 clockwise from (-27.5, -30) to (-36, -25.2678)
  arc A2 centre (27.5, -20) radius 10 clockwise from (36, -25.2678) to (27.5, -30)
  arc A3 centre (27.5, -20) radius 12 clockwise from (36, -28.4705) to (27.5, -32)
  arc A4 centre (-27.5, -20) radius 12 clockwise from (-27.5, -32) to (-36, -28.4705)
  point P10 (-36, -28.4705)
  point P14 (-36, -28.4705)
  point P16 (36, -28.2236)
  point P4 (-19.5, -30)
  point P18 (-19.5, -30)
  point P5 (21.9, -30)
  point P19 (21.9, -30)
  point P28 (21.9, -32)
  point P29 (-19.5, -32)
  point P20 (16.6, -26)
  point P30 (16.6, -26)
  point P21 (16.6, -28)
  point P31 (16.6, -28)
  point P22 (-16.6, -26)
  point P32 (-16.6, -26)
  point P23 (-16.6, -28)
  point P33 (-16.6, -28)
  point P35 (-17.5, -32)
  point P37 (19.9, -32)
  coincident P10 P14
  parallel L6 L8
  coincident L7 P16
  coincident P4 P18
  perpendicular L4 L10
  coincident P5 P19
  perpendicular L4 L11
  coincident L5 P28
  coincident L5 P29
  coincident P20 P30
  coincident P21 P31
  coincident P22 P32
  coincident P23 P33
  coincident L5 P35
  perpendicular L5 L22
  coincident L5 P37
  perpendicular L5 L23
extrude "Extrude73" cut sketch "Sketch20" profile of L8 L9 L10 L13 against normal blind 11
extrude "Extrude74" add sketch "Sketch20" profile of L1 L3 L6 L7 L11 L12 L15 L16 L17 L18 to an object
extrude "Extrude75" add sketch "Sketch21" profile of L1 L2 L3 L4 L12 L13 L14 L15 L16 L17 L18 L19 L20 L21 L22 L23 L24 L25 to an object
extrude "Extrude76" add sketch "Sketch21" profile of L1 L2 L3 L4 L12 L13 L14 L15 L16 L17 L18 L19 L20 L21 L22 L23 L24 L25 to an object
extrude "Extrude77" cut of existing geometry blind -42
extrude "Extrude78" cut of existing geometry blind -41
extrude "Extrude79" cut sketch "Sketch21" profile of L4 L5 L6 L7 L9 L10 L11 A1 L26 A2 L27 A3 L28 A4 L29 against normal blind 55 and along normal blind 90
extrude "Extrude80" cut of existing geometry blind 10
extrude "Extrude81" cut of existing geometry blind 9
extrude "Extrude82" cut of existing geometry blind -2
extrude "Extrude83" cut of existing geometry blind -2
combine "Combine8"
fillet "Fillet20" radius 1.5
fillet "Fillet22" radius 2
fillet "Fillet23" radius 1
remove_body "RemoveBody26"
fillet "Fillet24" radius 2
extrude "Extrude84" cut sketch "Sketch19" profile of A1 A2 L2 L4 A4 A3 L5 L6 L7 L8 against normal blind 130
extrude "Extrude85" cut sketch "Sketch19" profile of A1 A2 L2 L4 A4 A3 L5 L6 L7 L8 along normal blind 190
extrude "Extrude86" new body sketch "Sketch19" profile of A1 A2 L2 L4 A4 A3 L5 L6 L7 L8 against normal blind 55 bodies "chamber"
extrude "Extrude87" add sketch "Sketch19" profile of A1 A2 L2 L4 A4 A3 L5 L6 L7 L8 along normal blind 55
sketch "Sketch22" plane through (0, 0, 34.7705) normal (0, 0, 1) x axis (-1, 0, 0)
  line L1 (17.5, 9) -> (-17.5, 9)
  line L2 (17.5, 55) -> (17.5, 9)
  line L3 (-17.5, 55) -> (17.5, 55)
  line L4 (-17.5, 9) -> (-17.5, 55)
  line L5 (-17.5, -9) -> (17.5, -9)
  line L6 (-17.5, -55) -> (-17.5, -9)
  line L7 (17.5, -55) -> (-17.5, -55)
  line L8 (17.5, -9) -> (17.5, -55)
  line L9 (-17.5, 9) -> (17.5, 55)
  line L10 (33.2666, 0.3452) -> (-30, 0.3452)
  line L11 (0, 20) -> (0, 0)
  circle C1 centre (10, 45.1429) radius 0.9
  circle C2 centre (10, 45.1429) radius 3
  circle C3 centre (-10, 45.1429) radius 0.9
  circle C4 centre (-10, 45.1429) radius 3
  circle C5 centre (-10, -44.4524) radius 3
  circle C6 centre (-10, -44.4524) radius 0.9
  circle C7 centre (10, -44.4524) radius 0.9
  circle C8 centre (10, -44.4524) radius 3
  point P4 (17.5, 55)
  point P10 (17.5, 55)
  point P2 (-17.5, 9)
  point P11 (-17.5, 9)
  point P1 (0, 0)
  point P14 (0, 0)
  point P16 (10, 45.1429)
  point P17 (10, 45.1429)
  point P18 (-10, 45.1429)
  coincident P4 P10
  coincident P2 P11
  parallel L1 L10
  coincident P1 P14
  perpendicular L1 L11
  coincident L9 P16
  concentric C1 C2
  symmetric L11 C1 C3
  symmetric L11 C2 C4
  symmetric L10 C1 C7
  symmetric L10 C2 C8
  symmetric L10 C3 C6
  symmetric L10 C4 C5
  dimension "d351" diameter C1 = 1.8
  dimension "d352" diameter C2 = 6
  dimension "d500" distance P17 P18 = 20
sketch "speakerchamber" plane through (54.4239, 0, 0) normal (-1, 0, 0) x axis (0, -1, 0)
  line L1 (-2.4939, -25.92) -> (2.5561, -25.92)
  line L2 (2.5561, 25.59) -> (-2.4939, 25.59)
  line L3 (-2.4939, 27.61) -> (2.5561, 27.61)
  line L4 (2.5561, -27.94) -> (-2.4939, -27.94)
  line L5 (30.3311, -0.165) -> (-30.2689, -0.165)
  line L6 (30.3311, -5.165) -> (-30.2689, -5.165)
  line L7 (30.3311, 4.835) -> (-30.2689, 4.835)
  line L8 (-2.4939, -5.165) -> (-2.4939, -0.165)
  line L9 (-13.9653, -25.4604) -> (-13.131, -23.6207)
  line L10 (-13.9653, -25.4604) -> (-13.131, -23.6207)
  line L11 (-13.9653, -25.4604) -> (-13.131, -23.6207)
  line L12 (9.0797, -27.163) -> (8.2715, -25.2778)
  arc A1 centre (2.5561, -0.165) radius 25.755 clockwise from (2.5561, 25.59) to (2.5561, -25.92)
  arc A2 centre (-2.4939, -0.165) radius 25.755 clockwise from (-2.4939, -25.92) to (-2.4939, 25.59)
  arc A3 centre (2.5561, -0.165) radius 27.775 clockwise from (2.5561, 27.61) to (2.5561, -27.94)
  arc A4 centre (-2.4939, -0.165) radius 27.775 clockwise from (-2.4939, -27.94) to (-2.4939, 27.61)
  circle C1 centre (0.0311, -0.165) radius 5
  circle C2 centre (0.0311, -0.165) radius 2.15
  circle C3 centre (0.0311, -0.165) radius 1.6
  point P12 (-30.2689, -0.165)
  point P13 (30.3311, -0.165)
  point P7 (-2.4939, -0.165)
  point P18 (-2.4939, -0.165)
  point P19 (-13.9653, -25.4604)
  point P20 (-2.4939, -5.165)
  point P23 (9.0797, -27.163)
  point P24 (-13.131, -23.6207)
  point P25 (8.2715, -25.2778)
  midpoint A4 P12
  midpoint A3 P13
  coincident P7 P18
  coincident A4 P19
  coincident L6 P20
  perpendicular L6 L8
  coincident A3 P23
  coincident A2 P24
  coincident A1 P25
  tangent L7 C1
  concentric C1 C2
  concentric C1 C3
  dimension "d363" = 5
  dimension "d364" = -5
  dimension "d381" diameter C2 = 4.3
  dimension "d382" diameter C3 = 3.2
extrude "Extrude92" new body sketch "speakerchamber" profile of A1 A2 L2 A3 L3 A4 L6 L7 L10 L9 L11 L12 along normal blind 22
combine "Combine9" bodies "connect"
extrude "Extrude93" add sketch "speakerchamber" profile of A1 A2 A3 A4 L6 L7 against normal blind 3
extrude "Extrude4" cut sketch "speakerchamber" against normal blind 4
remove_body "RemoveBody27"
combine "Combine10"
remove_body "RemoveBody28"
position "Position9"
extrude "Extrude96" add sketch "speakerchamber" profile of C1 to an object
extrude "Extrude97" cut sketch "speakerchamber" along normal blind 2.5
combine "Combine12" bodies "connect"
extrude "Extrude98" cut sketch "speakerchamber" profile of C2 C3 along normal blind 2.5
extrude "Extrude5" cut sketch "speakerchamber" profile of C2 C3 against normal blind 2
extrude "Extrude99" add sketch "speakerchamber" profile of C1 C2 against normal blind 2
extrude "Extrude6" cut sketch "speakerchamber" profile of C1 C2 against normal blind 2
extrude "Extrude7" add of existing geometry blind 1
position "Position10"
extrude "Extrude8" add of existing geometry blind 6
extrude "Extrude9" add of existing geometry blind 6
extrude "Extrude10" cut of existing geometry blind -6
chamfer "Chamfer1" distance 1
external_derived "Sketch1"
derived_instance "DerivedInstance5"
position "Position11"
position "Position12"
sketch "typec" plane through (-33.7562, 0, 0) normal (-1, 0, 0) x axis (0, -1, 0)
  line L1 (-4.48, -59.7898) -> (-4.48, -58.7898)
  line L2 (3.48, -60.7898) -> (-3.48, -60.7898)
  line L3 (4.48, -58.7898) -> (4.48, -59.7898)
  line L4 (-3.48, -57.7898) -> (3.48, -57.7898)
  line L5 (3.2237, -58.0461) -> (-3.2237, -58.0461)
  line L6 (4.2237, -59.5336) -> (4.2237, -59.0461)
  line L7 (-3.2237, -60.5336) -> (3.2237, -60.5336)
  line L8 (-4.2237, -59.0461) -> (-4.2237, -59.5336)
  line L9 (0, -57.7898) -> (0, -60.7898)
  line L10 (-5.55, -56.1756) -> (5.55, -56.1756)
  line L11 (-5.55, -62.2756) -> (-5.55, -56.1756)
  line L12 (5.55, -62.2756) -> (-5.55, -62.2756)
  line L13 (5.55, -56.1756) -> (5.55, -62.2756)
  line L14 (-5.55, -62.2756) -> (5.55, -56.1756)
  line L15 (5.55, -62.2756) -> (-5.55, -56.1756)
  line L16 (-4.68, -59.7898) -> (-4.68, -58.7898)
  line L17 (3.48, -60.9898) -> (-3.48, -60.9898)
  line L18 (4.68, -58.7898) -> (4.68, -59.7898)
  line L19 (-3.48, -57.5898) -> (3.48, -57.5898)
  line L20 (-17.802, -55) -> (17.802, -55)
  line L21 (7.55, -55) -> (7.55, -56.1756)
  line L22 (7.55, -56.1756) -> (7.55, -62.2756)
  line L23 (7.55, -64.7626) -> (7.55, -62.2756)
  line L24 (-7.55, -55) -> (-7.55, -56.1756)
  line L25 (-7.55, -62.2756) -> (-7.55, -56.1756)
  line L26 (-7.55, -64.7626) -> (-7.55, -62.2756)
  arc A1 centre (-3.48, -58.7898) radius 1 clockwise from (-4.48, -58.7898) to (-3.48, -57.7898)
  arc A2 centre (-3.48, -59.7898) radius 1 clockwise from (-3.48, -60.7898) to (-4.48, -59.7898)
  arc A3 centre (3.48, -59.7898) radius 1 clockwise from (4.48, -59.7898) to (3.48, -60.7898)
  arc A4 centre (3.48, -58.7898) radius 1 clockwise from (3.48, -57.7898) to (4.48, -58.7898)
  arc A5 centre (3.2237, -59.0461) radius 1 clockwise from (3.2237, -58.0461) to (4.2237, -59.0461)
  arc A6 centre (3.2237, -59.5336) radius 1 clockwise from (4.2237, -59.5336) to (3.2237, -60.5336)
  arc A7 centre (-3.2237, -59.5336) radius 1 clockwise from (-3.2237, -60.5336) to (-4.2237, -59.5336)
  arc A8 centre (-3.2237, -59.0461) radius 1 clockwise from (-4.2237, -59.0461) to (-3.2237, -58.0461)
  arc A9 centre (-3.48, -59.7898) radius 1.2 clockwise from (-3.48, -60.9898) to (-4.68, -59.7898)
  arc A10 centre (3.48, -59.7898) radius 1.2 clockwise from (4.68, -59.7898) to (3.48, -60.9898)
  arc A11 centre (3.48, -58.7898) radius 1.2 clockwise from (3.48, -57.5898) to (4.68, -58.7898)
  arc A12 centre (-3.48, -58.7898) radius 1.2 clockwise from (-4.68, -58.7898) to (-3.48, -57.5898)
  arc A13 centre (0, 0) radius 65 clockwise from (34.641, -55) to (-34.641, -55)
  point P26 (0, -60.7898)
  point P27 (0, -57.7898)
  point P32 (0, -59.2256)
  point P30 (-5.55, -62.2756)
  point P31 (5.55, -62.2756)
  point P29 (-5.55, -56.1756)
  midpoint L2 P26
  midpoint L4 P27
  horizontal L10
  perpendicular L10 L11
  parallel L10 L12
  parallel L11 L13
  coincident L14 P32
  coincident L15 P32
  coincident L9 P32
  dimension "d446" distance P30 P31 = 11.1
  dimension "d447" distance P29 P30 = 6.1
  dimension "d448" = 0.2
  dimension "d456" = -2
  dimension "d457" = 2
extrude "Extrude117" add sketch "typec" profile of A1 L1 A2 L2 A3 L3 A4 L4 L5 A5 L6 A6 L7 A7 L8 A8 L10 L11 L12 L13 A11 L18 A10 A12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 to an object
extrude "Extrude118" cut sketch "typec" profile of A1 L1 A2 L2 A3 L3 A4 L4 L5 A5 L6 A6 L7 A7 L8 A8 L10 L11 L12 L13 A11 L18 A10 A12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 along normal blind 24
fillet "Fillet26" radius 13
fillet "Fillet27" radius 1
